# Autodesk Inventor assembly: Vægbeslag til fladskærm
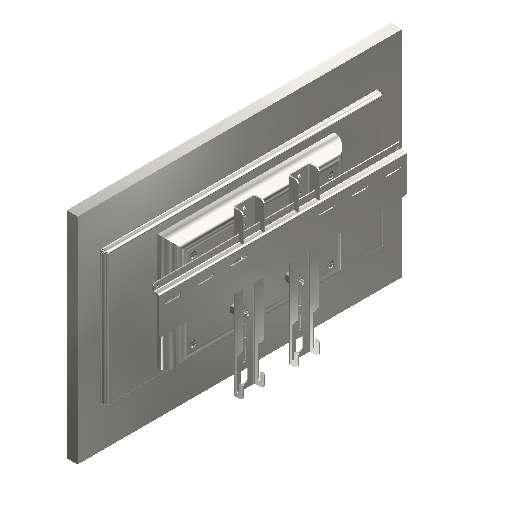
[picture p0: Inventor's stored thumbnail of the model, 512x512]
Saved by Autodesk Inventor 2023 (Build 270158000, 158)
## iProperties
Created: 2022-11
Part Number: Vægbeslag til fladskærm
Document SubType Name: Assembly
Designer: Lars Bertram Pedersen
Author: Cadskolen
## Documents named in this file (18)
- C:\INV GR\Vægbeslag til fladskærm\Vægbeslag til fladskærm.iam
- C:\INV GR\Vægbeslag til fladskærm\beslag  A.ipt
- C:\INV GR\Vægbeslag til fladskærm\beslag  B.ipt
- C:\INV GR\Vægbeslag til fladskærm\bøsning.ipt
- C:\INV GR\Vægbeslag til fladskærm\skærm.ipt
- C:\INV GR\Vægbeslag til fladskærm\ISO 1580 M6x40.ipt
- C:\INV GR\Vægbeslag til fladskærm\bagplade.ipt
- C:\INV GR\INV GR Assembly\ISO 7090 - 6 - 140 HV(1).ipt
- C:\INV GR\INV GR Assembly\ISO 4762 - M5 x 35ISO.ipt
- G:\Mit drev\CAD Skolen 2023\INV GR\INV GR Part\beslag  A.ipt
- G:\Mit drev\CAD Skolen 2023\INV GR\INV GR Part\beslag  B.ipt
- G:\Mit drev\CAD Skolen 2023\INV GR\INV GR Part\bøsning.ipt
- G:\Mit drev\CAD Skolen 2023\INV GR\INV GR Part\skærm.ipt
- G:\Mit drev\CAD Skolen 2023\INV GR\INV GR Part\ISO 1580 M6x40.ipt
- G:\Mit drev\CAD Skolen 2023\INV GR\INV GR Part\bagplade.ipt
- G:\Mit drev\CAD Skolen 2023\INV GR\INV GR Assembly\ISO 7090 - 6 - 140 HV(1).ipt
- G:\Mit drev\CAD Skolen 2023\INV GR\INV GR Assembly\ISO 4762 - M5 x 35ISO.ipt
- D:\CAD Skolen\INV GR\INV GR Assembly\Vægbeslag til fladskærm.iam
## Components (25 placed, 8 different names)
1. bagplade:1
2. beslag  A:1 — Mate:10, Mate:11, Mate:15
3. beslag  B:1 — Mate:10, Mate:11, Flush:1, Angle:2, Angle:3, Angle:4, Angle:5
4. skærm:1 — Mate:26, Flush:1, Mate:35, Angle:1
5. beslag  A:2 — Mate:18, Mate:19, Mate:22
6. bøsning:1 — Insert:26
7. bøsning:2 — Mate:15, Insert:25
8. bøsning:3 — Mate:19, Insert:27
9. bøsning:4 — Mate:18
10. ISO 1580 M6x40:1 — Mate:40, Angle:4
11. ISO 1580 M6x40:2 — Mate:42, Angle:5
12. ISO 1580 M6x40:3 — Mate:36, Angle:2
13. ISO 1580 M6x40:4 — Mate:38, Angle:3
14. ISO 7090 - 6 - 140 HV(1):1
15. ISO 7090 - 6 - 140 HV(1):2
16. ISO 7090 - 6 - 140 HV(1):3
17. ISO 7090 - 6 - 140 HV(1):4
18. ISO 7090 - 6 - 140 HV(1):5
19. ISO 7090 - 6 - 140 HV(1):6
20. ISO 7090 - 6 - 140 HV(1):7
21. ISO 7090 - 6 - 140 HV(1):8
22. ISO 4762 - M5 x 35ISO:1
23. ISO 4762 - M5 x 35ISO:2
24. ISO 4762 - M5 x 35ISO:3
25. ISO 4762 - M5 x 35ISO:4
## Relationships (21: Mate 12, Angle 5, Insert 3, Flush 1)
- Mate:10: beslag  A:1 ↔ beslag  B:1
- Mate:11: beslag  A:1 ↔ beslag  B:1
- Mate:15: beslag  A:1 ↔ bøsning:2
- Mate:18: beslag  A:2 ↔ bøsning:4
- Mate:19: beslag  A:2 ↔ bøsning:3
- Mate:22: beslag  A:2
- Mate:26: skærm:1
- Flush:1: beslag  B:1 ↔ skærm:1
- Mate:35: skærm:1
- Angle:1: skærm:1
- Mate:36: ISO 1580 M6x40:3
- Mate:38: ISO 1580 M6x40:4
- Mate:40: ISO 1580 M6x40:1
- Mate:42: ISO 1580 M6x40:2
- Angle:2: beslag  B:1 ↔ ISO 1580 M6x40:3
- Angle:3: beslag  B:1 ↔ ISO 1580 M6x40:4
- Angle:4: beslag  B:1 ↔ ISO 1580 M6x40:1
- Angle:5: beslag  B:1 ↔ ISO 1580 M6x40:2
- Insert:25: bøsning:2
- Insert:26: bøsning:1
- Insert:27: bøsning:3
